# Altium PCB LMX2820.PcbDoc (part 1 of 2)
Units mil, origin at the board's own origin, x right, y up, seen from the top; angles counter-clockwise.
Board outline 4000 x 4000 mil, 4 copper layers (Top Layer, RF GND, Signal GND, Bottom Layer), stack 61.2 mil thick; 127 components, 75 nets, 393 pads, 472 vias.
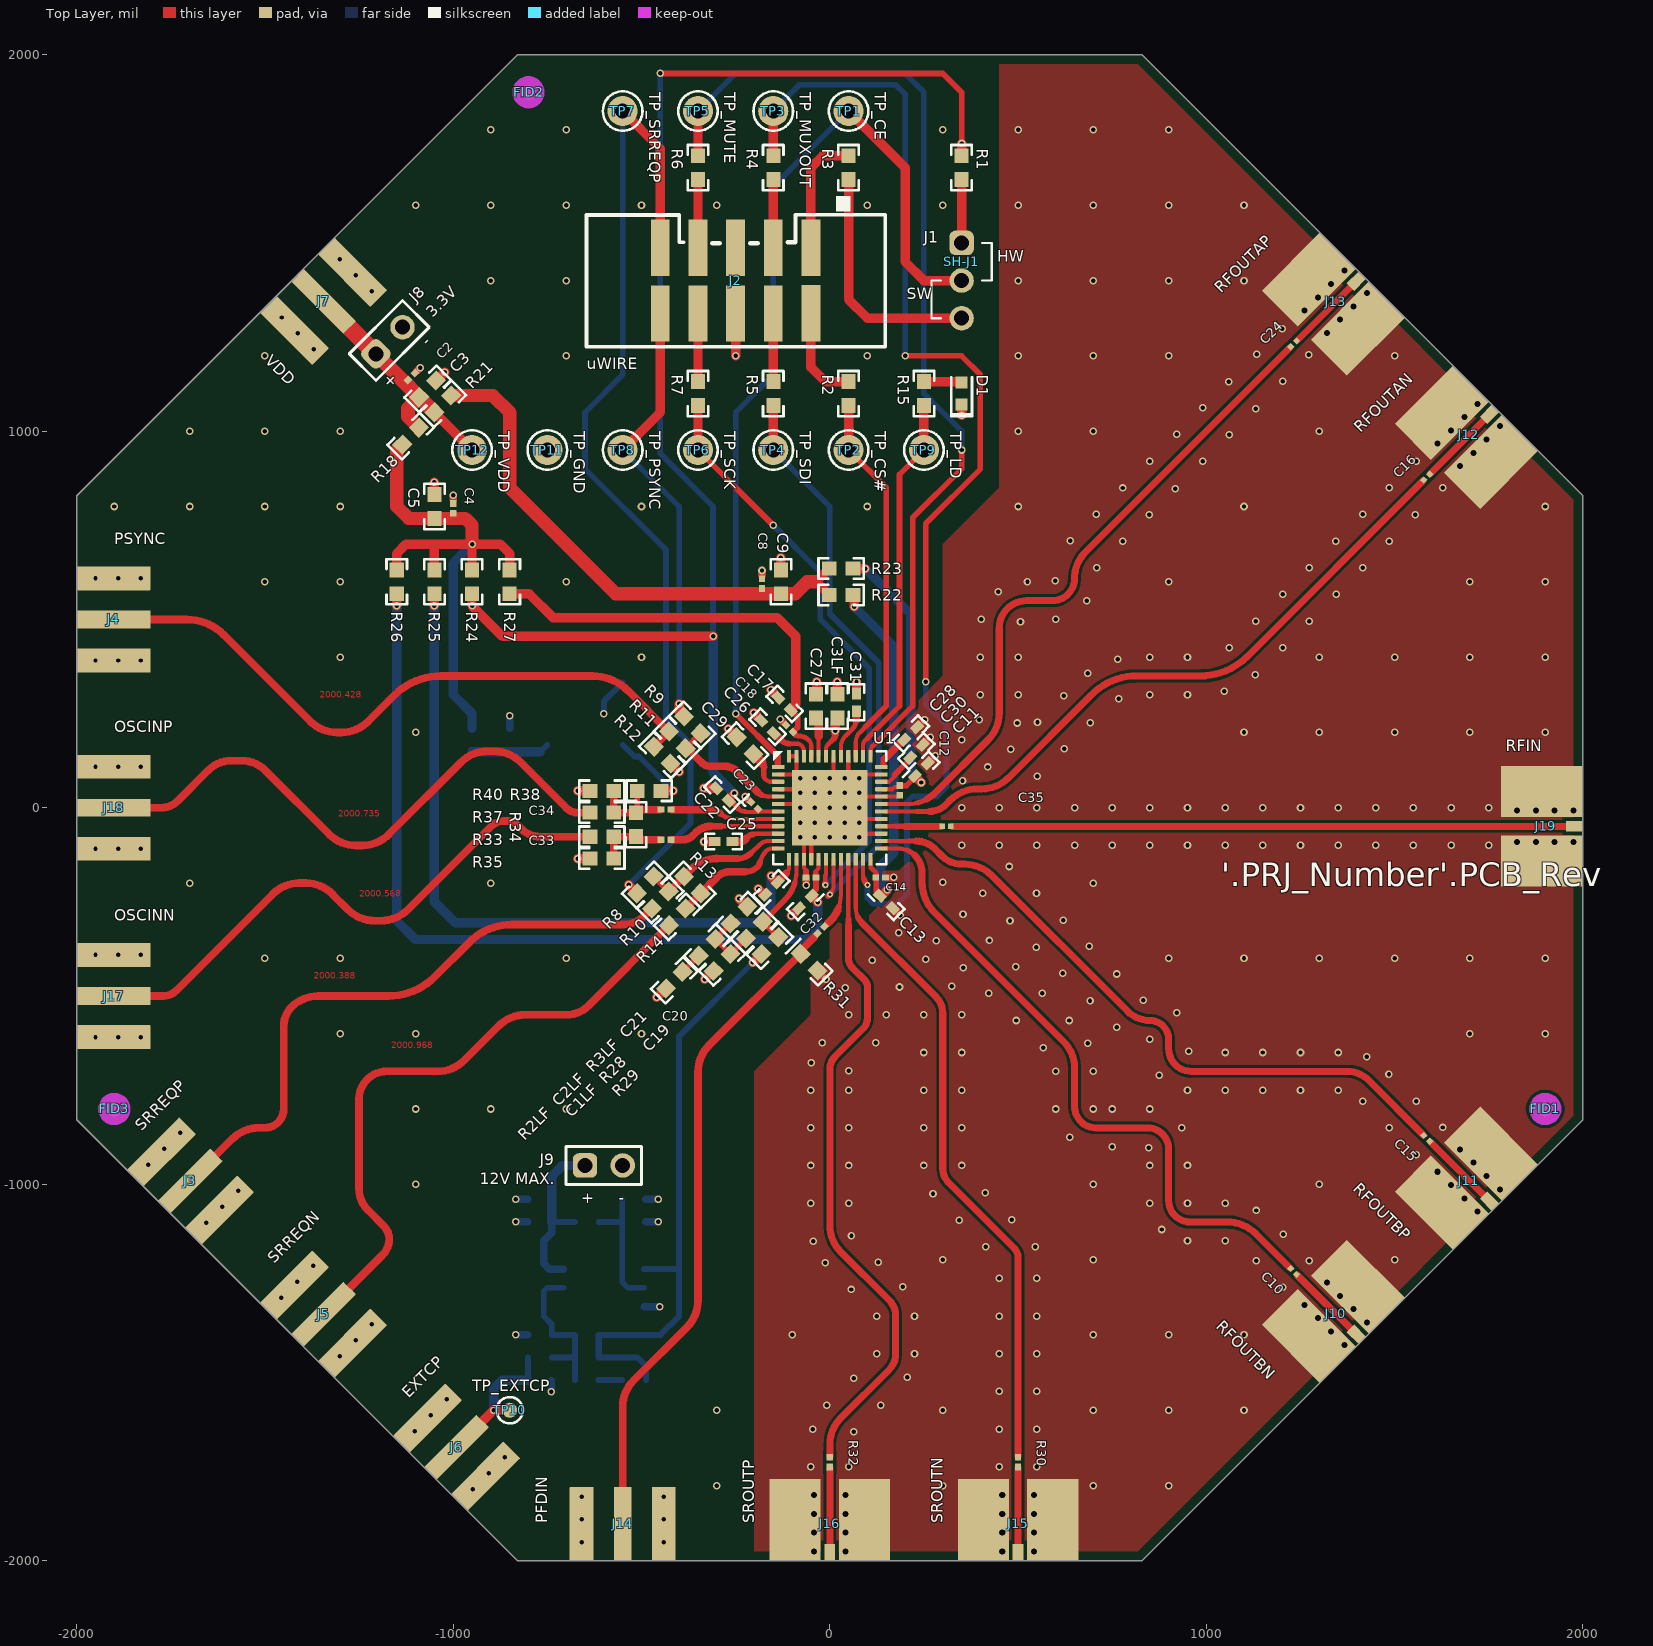
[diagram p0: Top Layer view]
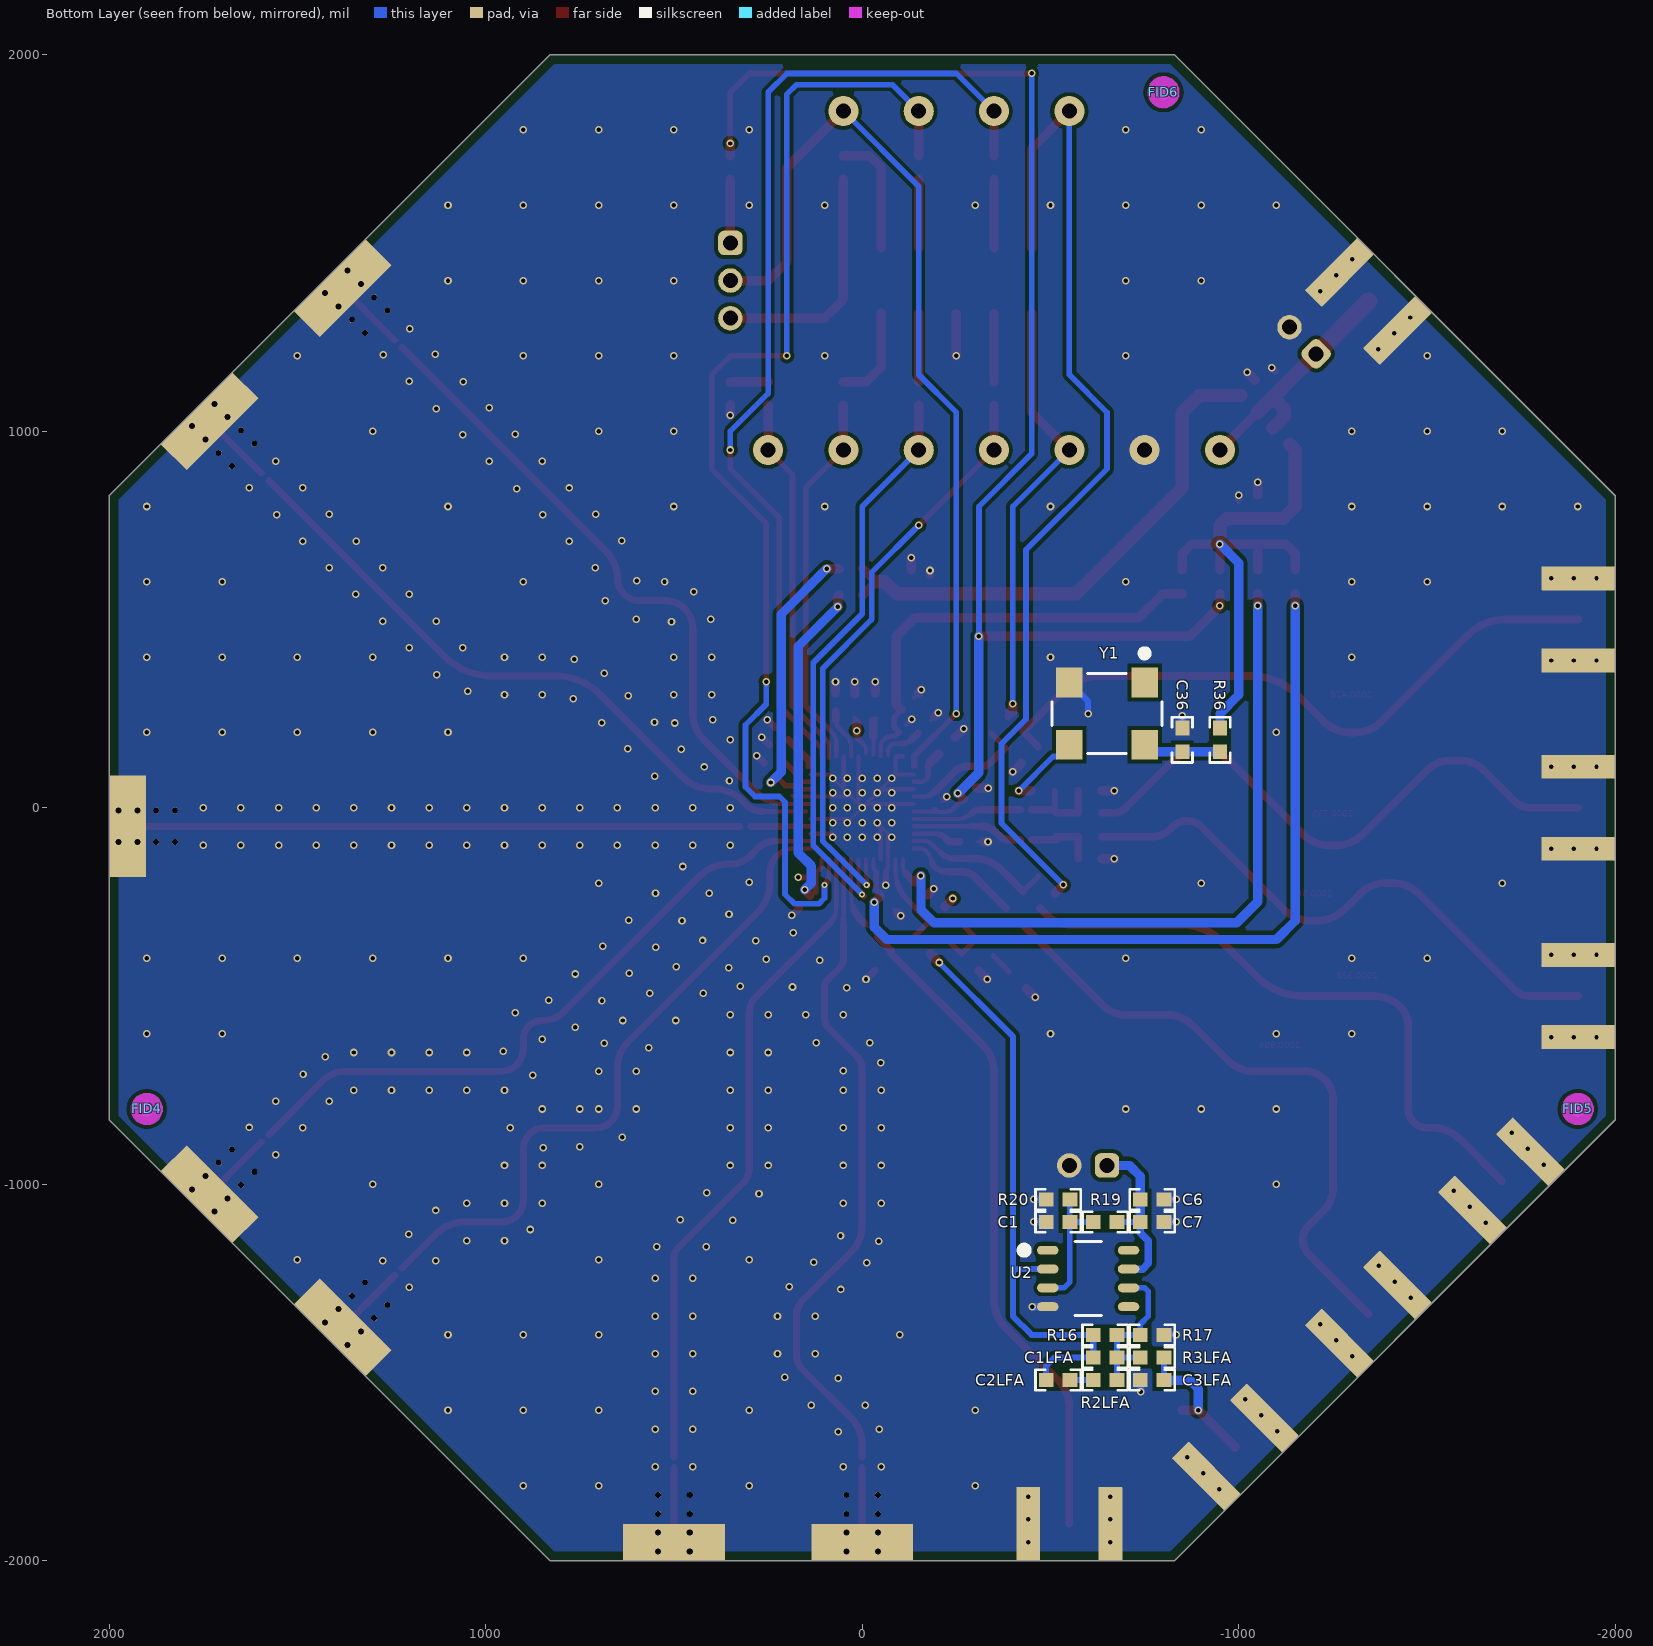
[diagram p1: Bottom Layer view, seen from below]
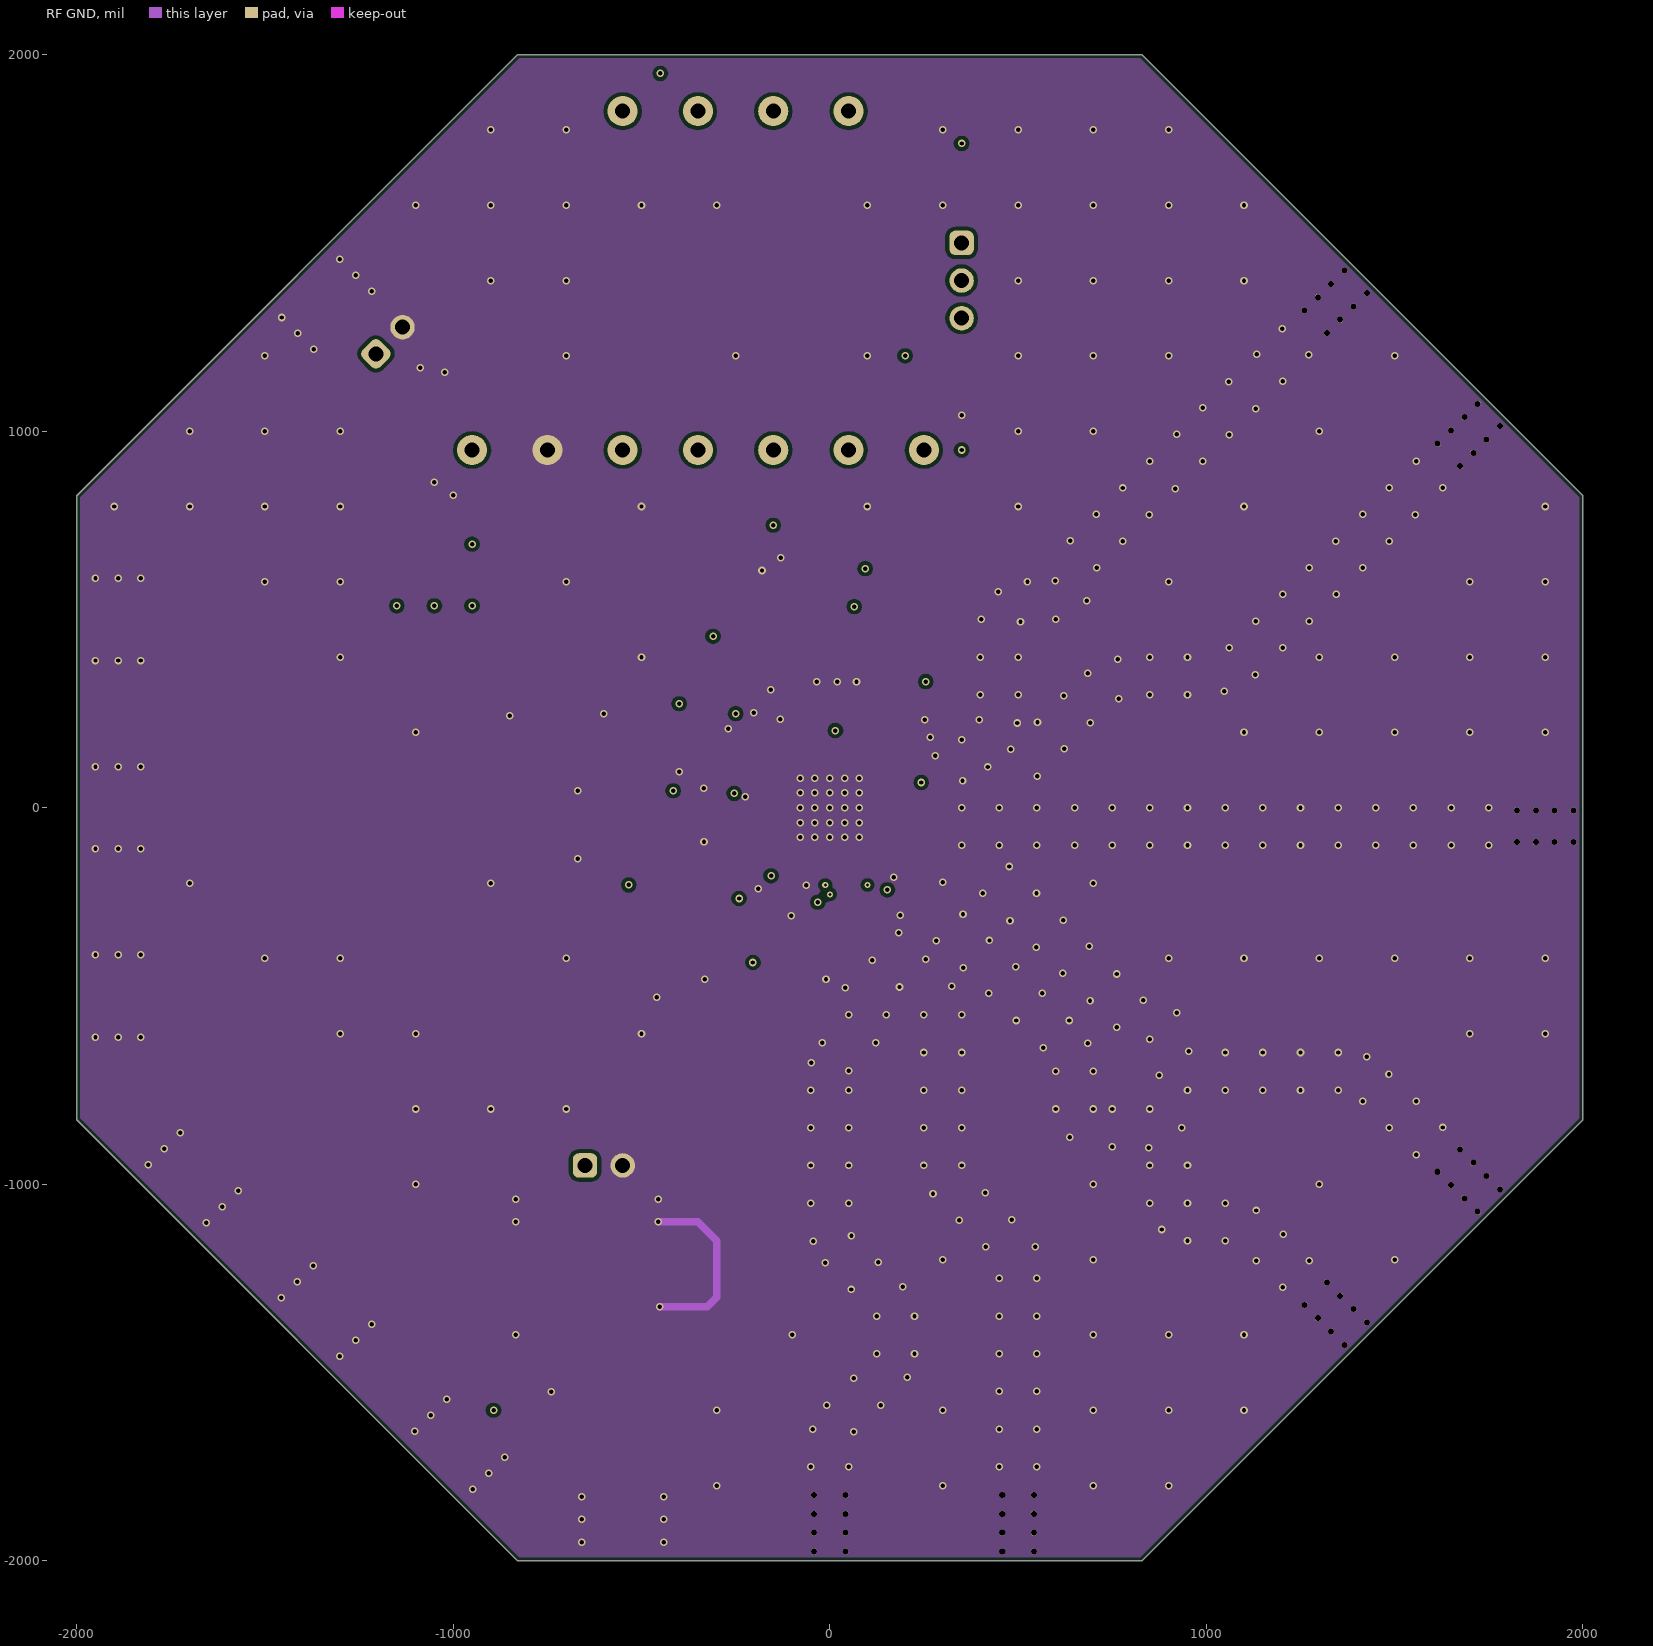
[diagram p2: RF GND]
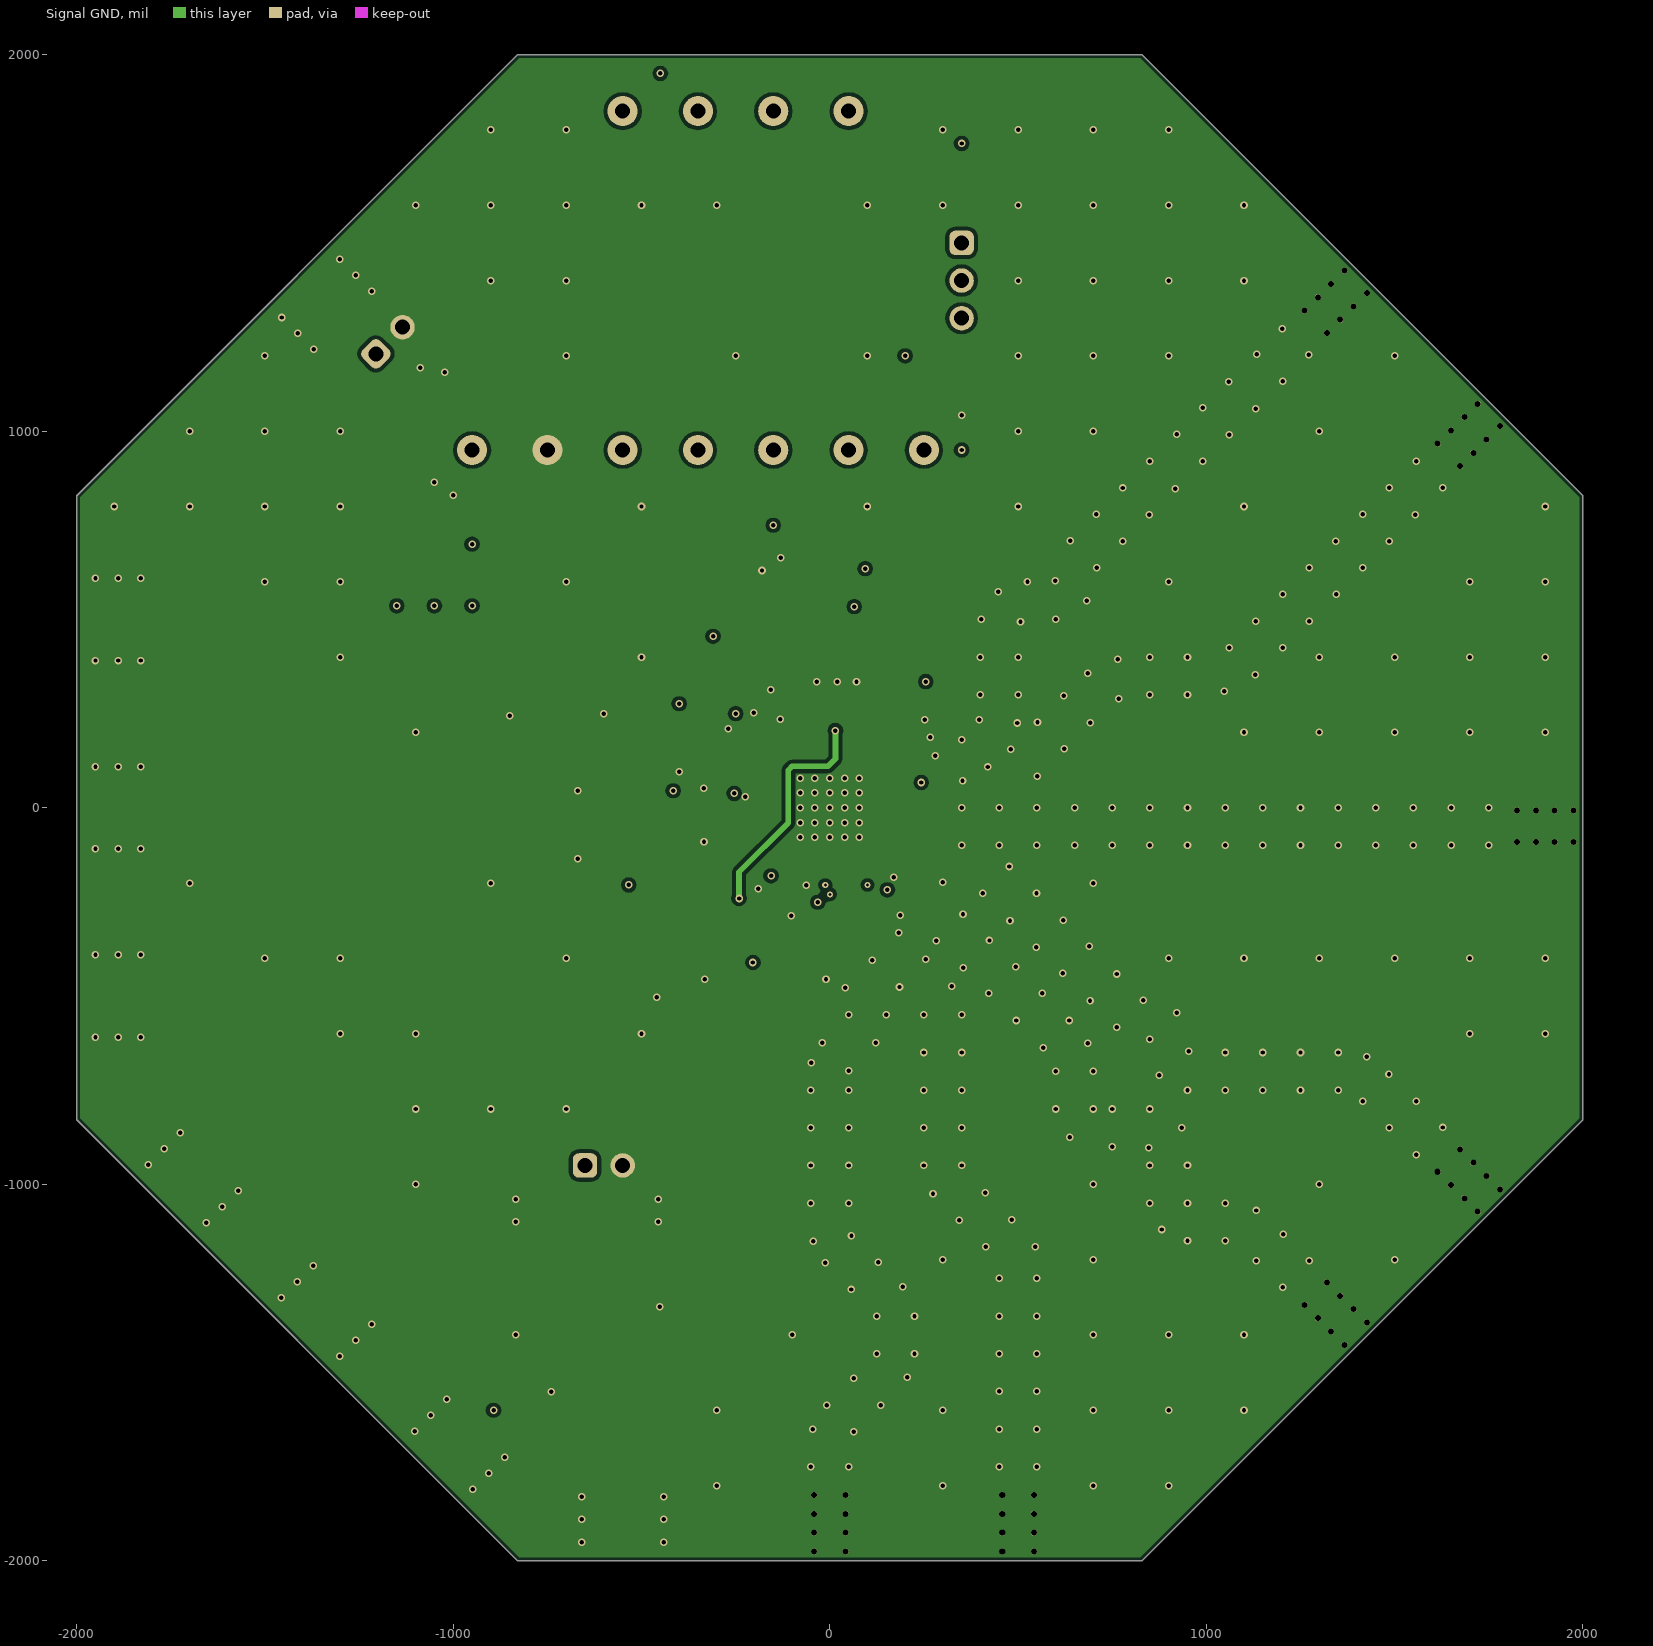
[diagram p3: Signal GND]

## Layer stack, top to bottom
Top Solder: solder mask 0.4, Solder Resist, Dk 3.5
Top Layer: signal copper 1.4
Dielectric 1: prepreg 10, Rogers R04350B, Dk 3.66
RF GND: signal copper 1.4
Dielectric 2: core 22.8, FR-4, Dk 4.2
Signal GND: signal copper 1.4
Dielectric 3: prepreg 22.8, FR-4, Dk 4.2
Bottom Layer: signal copper 1.4
Bottom Solder: solder mask 0.4, Solder Resist, Dk 3.5

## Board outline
-2000,-828.5 -2000,828.5 -828.5,2000 828.5,2000 2000,828.5 2000,-828.5 828.5,-2000 -828.5,-2000

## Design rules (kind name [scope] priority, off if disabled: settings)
AcuteAngle [All] p1: minimum=4.50000000000000E+0001 checktracksonly=FALSE
AssemblyTestPointUsage [All] p1: valid=2
BoardOutlineClearance BoardOutlineClearance_MountingHoles [OnCopper and InComponentClass('Mounting Holes')] p1: gap=39.37 ignorepadtopadclearanceinfootprint=FALSE
BoardOutlineClearance BoardOutlineClearance_Poly [OnCopper and IsPoly and not OnBottomLayer and not OnTopLayer] p2: gap=25 ignorepadtopadclearanceinfootprint=FALSE except(10: Poly-OutlineEdge)
BoardOutlineClearance [OnCopper and Not InComponentClass('Logo') and not InComponentClass('FiducialMark') and not InRegion(1000,500,4000,800) and not InPoly and not InComponent('RFOUTAP')and not InComponent('RFOUTAN')and not InComponent('RFOUTBP')and not InComponent('RFOUTBN')and not InComponent('OSCINP')and not InComponent('OSCINN')and not InComponent('SRREQP')and not InComponent ('SRREQN')and not InComponent ('SROUTP') and not InComponent ('SROUTN') and not InComponent ('PSYNC')and not InComponent('VDD')and not InComponent ('RFIN') and not InComponent ('PFDIN') and not InComponent ('EXTCP')and not IsPad and not InNet('NetJ16_1')and not InNet('NetJ15_1')and not InNet('NetC10_1')and not InNet('NetC15_1')and not InNet('NetJ19_1')and not InNet('NetC16_1')and not InNet('NetC24_1')and not InNet('NetC35_2')] p3: gap=75 ignorepadtopadclearanceinfootprint=FALSE except(25: Track-OutlineEdge Via-OutlineEdge Poly-OutlineEdge)
Clearance Clearance_Keepouts [((IsTrack Or IsArc) And Not InPoly) And IsFree and IsKeepOut vs ((IsTrack Or IsArc) And Not InPoly) And IsFree and IsKeepOut] p1: gap=0 ignorepadtopadclearanceinfootprint=FALSE
Clearance Clearance_Poly [InPolygon and not OnTopLayer] p2: gap=10 ignorepadtopadclearanceinfootprint=TRUE
Clearance Clearance_Poly_Top [InPolygon and OnTopLayer] p3: gap=10 ignorepadtopadclearanceinfootprint=TRUE except(8: Arc-Fill Arc-Poly Arc-Region Track-Fill Track-Poly Track-Region)
Clearance Clearance_FiducialMark [IsKeepOut and InComponentClass('FiducialMark') vs IsPad and InComponentClass('FiducialMark')] p4: gap=0 ignorepadtopadclearanceinfootprint=FALSE
Clearance [All] p5: gap=7.87 ignorepadtopadclearanceinfootprint=TRUE
ComponentClearance ComponentClearance_MountingHoles_FiducialMarks [InComponentClass('Mounting Holes') vs InComponentClass('FiducialMark')] p1: gap=50 collisioncheckmode=3 verticalgap=10 showdistances=FALSE
ComponentClearance ComponentClearance_Shunt [InComponentClass('Header') vs InComponentClass('Shunt')] p2: gap=0 collisioncheckmode=3 verticalgap=0 showdistances=FALSE
ComponentClearance ComponentClearance_Logo [InComponentClass('Logo')] p3: gap=50 collisioncheckmode=3 verticalgap=10 showdistances=FALSE
ComponentClearance ComponentClearance_ScrewToNut [(HasFootprint('NY PMS 440 0025 PH')) vs (HasFootprint('Keystone_1902C'))] p4: gap=5 collisioncheckmode=3 verticalgap=10 showdistances=FALSE
ComponentClearance ComponentClearance_MountingHoles [InComponentClass('Mounting Holes')] p5: gap=250 collisioncheckmode=3 verticalgap=100000 showdistances=FALSE
ComponentClearance ComponentClearance_SmallPassives [HasFootprint('0201*') or HasFootprint('0402*') or HasFootprint('0508') or HasFootprint('0603*') or HasFootprint('0612') or HasFootprint('0805*') or HasFootprint('0815*') or HasFootprint('0830*') or HasFootprint('1206*') or HasFootprint('1210*') or HasFootprint('1808*') or HasFootprint('1812*') or HasFootprint('1825*') or HasFootprint('2010*') or HasFootprint('2220*') or HasFootprint('2225*') or HasFootprint('2512*') or HasFootprint('2728*') or HasFootprint('3518*') vs HasFootprint('0201*') or HasFootprint('0402*') or HasFootprint('0508') or HasFootprint('0603*') or HasFootprint('0612') or HasFootprint('0805*') or HasFootprint('0815*') or HasFootprint('0830*') or HasFootprint('1206*') or HasFootprint('1210*') or HasFootprint('1808*') or HasFootprint('1812*') or HasFootprint('1825*') or HasFootprint('2010*') or HasFootprint('2220*') or HasFootprint('2225*') or HasFootprint('2512*') or HasFootprint('2728*') or HasFootprint('3518*')] p6: gap=14.96 collisioncheckmode=3 verticalgap=10 showdistances=FALSE
ComponentClearance ComponentClearance_THtoSMT [IsThruComponent vs IsSMTComponent] p7: gap=40 collisioncheckmode=3 verticalgap=30 showdistances=FALSE
ComponentClearance ComponentClearance_THtoTH [IsThruComponent vs IsThruComponent] p8: gap=30 collisioncheckmode=3 verticalgap=30 showdistances=FALSE
ComponentClearance [All] p9: gap=30 collisioncheckmode=3 verticalgap=10 showdistances=FALSE
DiffPairsRouting [All] p1: maxlimit=100 minlimit=10 mostfreqgap=10 toplayer_minwidth=15 toplayer_maxwidth=15 toplayer_prefwidth=15 midlayer1_minwidth=15 midlayer1_maxwidth=15 midlayer1_prefwidth=15 midlayer2_minwidth=15 midlayer2_maxwidth=15 midlayer2_prefwidth=15 bottomlayer_minwidth=15 bottomlayer_maxwidth=15 bottomlayer_prefwidth=15 maxuncoupledlength=1000
FabricationTestPointUsage TestPointUsage [All] p1: valid=2 allowmultiple=FALSE
FabricationTestpoint Testpoint [All] p1: side=3 testpointundercomponent=TRUE minsize=40 maxsize=100 preferedsize=60 minholesize=0 maxholesize=40 preferedholesize=32 testpointgrid=1 allowsidetop=TRUE allowsidebottom=TRUE usegrid=TRUE gridtolerance=0.01
FanoutControl Fanout_LCC [IsLCC] p1: bgadir=Out bgaviamode=Centered fanoutstyle=Auto fanoutdirection=Alternating viagrid=1 // Fanout_LCC (Default Rule)
FanoutControl Fanout_BGA [IsBGA] p2: bgadir=Out bgaviamode=Centered fanoutstyle=Auto fanoutdirection=Alternating viagrid=1 // Fanout_BGA (Default Rule)
FanoutControl Fanout_Default [All] p4: bgadir=Out bgaviamode=Centered fanoutstyle=Auto fanoutdirection=Alternating viagrid=1 // Fanout_Default (Default Rule)
FanoutControl Fanout_Small [(CompPinCount < 5)] p5: bgadir=Out bgaviamode=Centered fanoutstyle=Auto fanoutdirection=OutThenIn viagrid=1 // Fanout_Small (Default Rule)
HoleSize [All] p1: absolutevalues=TRUE maxlimit=251 minlimit=7.87 maxpercent=80.000 minpercent=20.000
MinimumAnnularRing MinimumAnnularRing_ThermalPadVias [IsVia and InAnyComponent] p1: minimumring=3.94
MinimumAnnularRing [All] p2: minimumring=4
MinimumSolderMaskSliver MinimumSolderMaskSliver_Logo [InComponentClass('Logo') vs InComponentClass('Logo')] p1: minsoldermaskwidth=0.7
MinimumSolderMaskSliver [All] p2: minsoldermaskwidth=3.94
PlaneConnect [All] p1: planeconnectstyle=Relief reliefexpansion=10 reliefentries=4 reliefconductorwidth=10 reliefairgap=10
PolygonConnect [All] p1: connectstyle=Direct reliefconductorwidth=10 reliefentries=4 polygonreliefangle="90 Angle" airgapwidth=10
RoutingVias ThermalPadVias [IsVia and InAnyComponent] p1: holewidth=7.87 width=19.68 viastyle="Through Hole" minholewidth=7.87 minwidth=19.68 maxholewidth=12.99 maxwidth=23.62
RoutingVias [All] p2: holewidth=13 width=25 viastyle="Through Hole" minholewidth=8 minwidth=15 maxholewidth=18 maxwidth=25
SilkToBoardRegionClearance [Not ((IsComment or IsDesignator) And (Hide <> 'False')) and not InRegion(1000,500,4000,800)] p1:
SilkToSilkClearance SilkToSilkClearance_Pb-FreeLogo [(HasFootprint('Pb-Free_Overlay_Medium') OR HasFootprint('Pb-Free_Overlay_Small')) vs (HasFootprint('Pb-Free_Overlay_Medium') OR HasFootprint('Pb-Free_Overlay_Small'))] p1: silktosilkclearance=0
SilkToSilkClearance [All] p2: silktosilkclearance=3.94
SilkToSolderMaskClearance SilkToComponentPadClearance [(IsPad or IsFill or IsRegion) and InAnycomponent] p1: minsilkscreentomaskgap=5 clearancetoexposedcopper=TRUE
SilkToSolderMaskClearance "Silk to Solder Mask Opening" [All] p2: minsilkscreentomaskgap=3.94 clearancetoexposedcopper=FALSE
SolderMaskExpansion [All] p1: expansion=1.97
UnRoutedNet [All] p1: checkbadconnections=TRUE
Width [All] p1: maxlimit=100 minlimit=6 preferedwidth=10 checkconnectedcopper=TRUE
14 further rules are at their usual default settings.

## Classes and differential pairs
component class Shunt: SH-J1
component class Header: J1 J8 J9
component class LMX2820_SYNTH: C1LF C2LF C3LF C10 C11 C12 C13 C14 C15 C16 C17 C18 C19 C20 C21 C22 C23 C24 C25 C26 C27 C28 C29 C30 C31 C32 C33 C34 C35 C36 J10 J11 J12 J13 J14 J15 J16 J17 J18 J19 R2LF R3LF R22 R23 R24 R25 R26 R27 R28 R29 R30 R31 R32 R33 R34 R35 R36 R37 R38 R40 R300 U1 Y1
component class LMX2820_HW: FID1 FID2 FID3 FID4 FID5 FID6 SH-J1
component class FiducialMark: FID1 FID2 FID3 FID4 FID5 FID6

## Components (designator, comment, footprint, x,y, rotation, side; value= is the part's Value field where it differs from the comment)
C1 "885012206046" 0603 -520,-1100 r180 bottom value=0.1uF
C1LF "885012006012" 0603 -286,-411 r225 top value=470pF
C1LFA "885012206046" 0603 -645,-1460 r180 bottom value=0.1uF
C2 "GRM033R61C104KE84D" 0201_033 -1111,1145 r45 top value=0.1uF
C2LF "885012206070" 0603 -326,-371 r225 top value=0.068uF
C2LFA "885012206046" 0603 -520,-1520 r180 bottom value=0.1uF
C3 "GRM188R61A106KAALD" 0603 -1068,1112.5 r45 top value=10uF
C3LF "885012206036" 0603 20.5,270 r90 top value=2200pF
C3LFA "885012206046" 0603 -770,-1520 r180 bottom value=0.1uF
C4 "GRM033R61C104KE84D" 0201_033 -1000,795 r90 top value=0.1uF
C5 "GRM188R61A106KAALD" 0603 -1050,800 r270 top value=10uF
C6 "885012206046" 0603 -770,-1040 r180 bottom value=0.1uF
C7 "GRM188R61A106KAALD" 0603 -770,-1100 r180 bottom value=10uF
C8 "GRM033R61C104KE84D" 0201_033 -180,595 r90 top value=0.1uF
C9 "GRM188R61A106KAALD" 0603 -130,600 r270 top value=10uF
C10 "ATC530Z104KT10T" 0201_033L 1231.65,-1231.65 r135 top locked value=0.1uF
C11 "GRM155R61E105KA12D" 0402 243,101 r45 top value=1uF
C12 "GRM033R61C104KE84D" 0201_033 186,46 r270 top value=0.1uF
C13 "GRM155R61E105KA12D" 0402 150,-250 r135 top value=1uF
C14 "GRM033R61C104KE84D" 0201_033 135,-185 r180 top value=0.1uF
C15 "ATC530Z104KT10T" 0201_033L 1585.15,-878.15 r135 top locked value=0.1uF
C16 "ATC530Z104KT10T" 0201_033L 1585.3,878.2 r225 top locked value=0.1uF
C17 "GRM155R61E105KA12D" 0402 -120,276 r135 top value=1uF
C18 "GRM033R61C104KE84D" 0201_033 -107,210 r135 top value=0.1uF
C19 "GRM155R61E105KA12D" 0402 -65,-250 r225 top value=1uF
C20 "GRM033R61C104KE84D" 0201_033 -50,-185 r0 top value=0.1uF
C21 "GRM155R61E105KA12D" 0402 -155,-214 r225 top value=1uF
C22 "GRM155R61E105KA12D" 0402 -285,35 r135 top value=1uF
C23 "GRM033R61C104KE84D" 0201_033 -200,5.5 r315 top value=0.1uF
C24 "ATC530Z104KT10T" 0201_033L 1231.75,1231.75 r225 top locked value=0.1uF
C25 "GRM155R61E105KA12D" 0402 -282,-90 r180 top value=1uF
C26 "GRM155R61E105KA12D" 0402 -165,215 r135 top value=1uF
C27 "GRM188R61A106KAALD" 0603 -37,270 r270 top value=10uF
C28 "GRM155R61E105KA12D" 0402 215,197 r225 top value=1uF
C29 "CGA3E3X7R1E474K080AB" 0603 -225,165 r135 top value=0.47uF
C30 "GRM155R61E105KA12D" 0402 230,150 r225 top value=1uF
C31 "GRM155R61E105KA12D" 0402 71,280 r90 top value=1uF
C32 "GRM033R61C104KE84D" 0201_033 -23,-325 r225 top value=0.1uF
C33 "GRM033R61C104KE84D" 0201_033 -435,-85 r180 top value=0.1uF
C34 "GRM033R61C104KE84D" 0201_033 -435,-5 r180 top value=0.1uF
C35 "ATC530Z104KT10T" 0201_033L 310,-49.21 r0 top value=0.1uF
C36 "885012206052" 0603 -850,180 r90 bottom value=1uF
D1 "LTST-C190GKT" LED_LTST-C190 350,1100 r270 top value=Green
FID1 "Fiducial" Fiducial10-20 1900,-800 r0 top
FID2 "Fiducial" Fiducial10-20 -800,1900 r0 top
FID3 "Fiducial" Fiducial10-20 -1900,-800 r0 top
FID4 "Fiducial" Fiducial10-20 1900,-800 r180 bottom
FID5 "Fiducial" Fiducial10-20 -1900,-800 r180 bottom
FID6 "Fiducial" Fiducial10-20 -800,1900 r180 bottom
J1 "TSW-103-07-G-S" TSW-103-07-G-S 350,1400 r270 top
J2 "uWIRE" FCI_52601-S10-8LF -250,1400 r270 top
J3 "SRREQP" FP-CON-SMA-EDGE-S_CONN_JACK-MFG -1900.3,-1193.2 r135 top locked
J4 "PSYNC" FP-CON-SMA-EDGE-S_CONN_JACK-MFG -2187.5,500 r90 top locked
J5 "SRREQN" FP-CON-SMA-EDGE-S_CONN_JACK-MFG -1546.5,-1547 r135 top locked
J6 "EXTCP" FP-CON-SMA-EDGE-S_CONN_JACK-MFG -1193.25,-1900.25 r135 top locked
J7 "VDD" FP-CON-SMA-EDGE-S_CONN_JACK-MFG -1546.5,1547 r45 top locked
J8 "3.3V" TSW-102-07-G-S -1170,1240.75 r45 top
J9 "12V MAX." TSW-102-07-G-S -600,-950 r0 top
J10 "RFOUTBN" Johnson_142-0771-831 1414.25,-1414.25 r225 top locked
J11 "RFOUTBP" Johnson_142-0771-831 1767.8,-1060.7 r225 top locked
J12 "RFOUTAN" Johnson_142-0771-831 1767.8,1060.7 r315 top locked
J13 "RFOUTAP" Johnson_142-0771-831 1414.25,1414.25 r315 top locked
J14 "PFDIN" FP-CON-SMA-EDGE-S_CONN_JACK-MFG -550,-2187.5 r180 top locked
J15 "SROUTN" Johnson_142-0771-831 500,-2000 r180 top locked
J16 "SROUTP" Johnson_142-0771-831 0,-2000 r180 top locked
J17 "OSCINN" FP-CON-SMA-EDGE-S_CONN_JACK-MFG -2187.5,-500 r90 top locked
J18 "OSCINP" FP-CON-SMA-EDGE-S_CONN_JACK-MFG -2187.5,0 r90 top locked
J19 "RFIN" Johnson_142-0771-831 2000,-49.21 r270 top locked
R1 "CRCW06031K00JNEA" 0603 350,1700 r90 top value=1.0k
R2 "CRCW060333R0JNEA" 0603 50,1100 r270 top value=33
R2LF "CRCW060368R1FKEA" 0603 -413,-458 r45 top value=68.1
R2LFA "CRCW060333R0JNEA" 0603 -645,-1520 r180 bottom value=33
R3 "CRCW060333R0JNEA" 0603 50,1700 r90 top value=33
R3LF "CRCW060318R2FKEA" 0603 -241,-285 r225 top value=18.2
R3LFA "CRCW06030000Z0EA" 0603 -770,-1460 r180 bottom value=0
R4 "CRCW060333R0JNEA" 0603 -150,1700 r90 top value=33
R5 "CRCW060333R0JNEA" 0603 -150,1100 r270 top value=33
R6 "CRCW060333R0JNEA" 0603 -350,1700 r90 top value=33
R7 "CRCW060333R0JNEA" 0603 -350,1100 r270 top value=33
R8 "CRCW060333R0JNEA" 0603 -490,-205 r45 top value=33
R9 "CRCW060333R0JNEA" 0603 -365,220 r315 top value=33
R10 "CRCW06030000Z0EA" 0603 -450,-245 r225 top value=0
R11 "CRCW060318R0JNEA" 0603 -405,180 r315 top value=18
R12 "CRCW060349R9FKEA" 0603 -445,140 r135 top value=49.9
R13 "CRCW0603102RFKEA" 0603 -365,-205 r315 top value=102
R14 "CRCW06030000Z0EA" 0603 -405,-290 r225 top value=0
R15 "CRCW0603330RJNEA" 0603 250,1100 r270 top value=330
R16 "CRCW06030000Z0EA" 0603 -645,-1400 r180 bottom value=0
R17 "CRCW06030000Z0EA" 0603 -770,-1400 r180 bottom value=0
R18 "CRCW06030000Z0EA" 0603 -1113,987 r45 top value=0
R19 "CRCW06030000Z0EA" 0603 -645,-1100 r0 bottom value=0
R20 "CRCW06030000Z0EA" 0603 -520,-1040 r180 bottom value=0
R21 "CRCW06030000Z0EA" 0603 -1027.75,1072.25 r45 top value=0
R22 "CRCW06030000Z0EA" 0603 30.02,565.03 r180 top value=0
R23 "CRCW06030000Z0EA" 0603 30.02,635.03 r180 top value=0
R24 "CRCW06030000Z0EA" 0603 -950,600 r90 top value=0
R25 "CRCW06030000Z0EA" 0603 -1050,600 r90 top value=0
R26 "CRCW06030000Z0EA" 0603 -1150,600 r90 top value=0
R27 "CRCW06030000Z0EA" 0603 -850,600 r90 top value=0
R28 "CRCW06030000Z0EA" 0603 -200,-325 r45 top value=0
R29 "CRCW06030000Z0EA" 0603 -159,-366 r45 top value=0
R30 "CRCW02010000Z0ED" 0201 500,-1738 r270 top locked value=0
R31 "CRCW060349R9FKEA" 0603 -55,-410 r135 top value=49.9
R32 "CRCW02010000Z0ED" 0201 0,-1738 r270 top locked value=0
R33 "CRCW06030000Z0EA" 0603 -605,-77 r0 top value=0
R34 "CRCW0603102RFKEA" 0603 -515,-45 r90 top value=102
R35 "CRCW060349R9FKEA" 0603 -605,-135 r0 top value=49.9
R36 "CRCW06033R30JNEA" 0603 -950,180 r90 bottom value=3.3
R37 "CRCW06030000Z0EA" 0603 -605,-13 r0 top value=0
R38 "CRCW06030000Z0EA" 0603 -480,45 r180 top value=0
R40 "CRCW060349R9FKEA" 0603 -605,45 r180 top value=49.9
SH-J1 "SNT-100-BK-G" SNT-100-BK-G 350,1450 r90 top value=1x2
TP1 "TP_CE" Keystone5002 50,1850 r180 top
TP2 "TP_CS#" Keystone5002 50,950 r180 top
TP3 "TP_MUXOUT" Keystone5002 -150,1850 r180 top
TP4 "TP_SDI" Keystone5002 -150,950 r180 top
TP5 "TP_MUTE" Keystone5002 -350,1850 r180 top
TP6 "TP_SCK" Keystone5002 -350,950 r180 top
TP7 "TP_SRREQP" Keystone5002 -550,1850 r90 top
TP8 "TP_PSYNC" Keystone5002 -550,950 r180 top
TP9 "TP_LD" Keystone5002 250,950 r90 top
TP10 "TP_EXTCP" TESTPOINT -850,-1600 r0 top
TP11 "TP_GND" Keystone5001 -750,950 r90 top
TP12 "TP_VDD" Keystone5000 -950,950 r90 top
U1 "LMX2820" RTC0048A 0,0 r0 top locked
U2 "LME49710MA" D0008A_N -600,-1250 r180 bottom
Y1 "CWX813-100.0M" OSC_CWX -650,250 r270 bottom

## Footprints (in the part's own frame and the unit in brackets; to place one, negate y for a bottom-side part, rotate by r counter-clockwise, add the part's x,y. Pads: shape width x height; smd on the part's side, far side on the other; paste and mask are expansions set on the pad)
0201 [mm] "Data from Kemet datasheet CC101_COM dated 7/28/11"
  rect 0.46x0.42 smd mask+0.048: 1(-0.33,0) 2(0.33,0)
  body extent -0.31,-0.16 0.31,0.16, height 0.26
0201_033 [mm] "SMD, 2-Leads, Height 0.33mm"
  rect 0.46x0.42 smd mask+0.048: 1(-0.33,0) 2(0.33,0)
  body extent -0.31,-0.16 0.31,0.16, height 0.33
0201_033L [mm] "0201"
  rect 0.36x0.356 smd mask+0.048: 1(-0.28,0) 2(0.28,0)
  body extent -0.31,-0.16 0.31,0.16, height 0.33
0402 [mm] "0402 from SM-752 data"
  rect 0.8x0.6 smd: 1(-0.6,0) 2(0.6,0)
  silkscreen extent -1.22,-0.52 1.22,0.52, body extent -0.55,-0.3 0.55,0.3, height 0.6
0603 [mm] "0603 from SM-752 data"
  rect 1x0.95 smd: 1(-0.8,0) 2(0.8,0)
  silkscreen extent -1.52,-0.69 1.52,0.69, body extent -0.87,-0.47 0.87,0.47, height 1
D0008A_N [mm] "SOIC, 8-Leads, Body 4.9x3.9mm, Pitch 1.27mm, IPC Medium Density"
  oval 1.45x0.6 smd: 1(-2.725,1.905) 2(-2.725,0.635) 3(-2.725,-0.635) 4(-2.725,-1.905) 5(2.725,-1.905) 6(2.725,-0.635) 7(2.725,0.635) 8(2.725,1.905)
  silkscreen extent -0.9,-2.5 0.9,2.5, body extent -3,-2.45 3,2.45, height 1.63
FCI_52601-S10-8LF [mil] "FCI Electronics"
  rect 150x50 smd: 1(-87.5,200) 2(86.5,200) 3(-87.5,100) 4(87.5,100) 5(-87.5,0) 6(87.5,0) 7(-87.5,-100) 8(87.5,-100) 9(-87.5,-200) 10(87.5,-200)
  silkscreen extent -224,-396 176,397, body extent -172,-395 173,395, height 496
Fiducial10-20 [mm]
  round 1 smd mask+0.5: 1(0,0)
  Top Layer keep-out circle w1.178: c0,0 r0.5
FP-CON-SMA-EDGE-S_CONN_JACK-MFG [mm]
  rrect8% 1.2x5 smd paste+0 mask+0: 1(0,-7.26)
  rrect6% 1.6x5 smd paste+0 mask+0: 2(-2.77,-7.26) 3(2.77,-7.26)
  rrect6% 1.6x5 smd far side paste+0 mask+0: 4(-2.77,-7.26) 5(2.77,-7.26)
  body extent -3.28,-9.86 3.28,4.86, height 0.25
Johnson_142-0771-831 [mil] "JACK, SMA, 50 Ohm, Gold, Edge Mount"
  rect 28.5x45 smd: 1(0,-22.5)
  rect 135.75x218 smd: 2(-92.13,-109) 3(92.13,-109)
  round 16 hole 16: 2(-42,-25) 2(-42,-175) 2(-42,-75) 2(-42,-125) 3(42,-125) 3(42,-25) 3(42,-75) 3(42,-175)
  rect 270x97.5 smd far side: 4(0,-48.75)
  body extent -124,-179 123,375, height 131
Keystone5000 [mil] "For Keystone 500x miniature loop terminals"
  round 80 hole 40: 1(0,0)
  silkscreen extent -52,-52 52,52, body extent -49,-49 49,49, height 182
Keystone5001 [mil] "For Keystone 500x miniature loop terminals"
  round 80 hole 40: 1(0,0)
  silkscreen extent -52,-52 52,52, body extent -49,-49 49,49, height 182
Keystone5002 [mil] "For Keystone 500x miniature loop terminals"
  round 80 hole 40: 1(0,0)
  silkscreen extent -52,-52 52,52, body extent -49,-49 49,49, height 182
LED_LTST-C190 [mm] "Lite-On"
  rect 0.8x0.8 smd: 1(-0.75,0) 2(0.75,0)
  silkscreen extent -1.1,-0.7 1.52,0.7, body extent -0.85,-0.45 0.85,0.45, height 0.9
OSC_CWX [mm] "CONNOR WINFIELD"
  rect 2x1.8 smd: 1(-2.1,2.54) 2(-2.1,-2.54) 3(2.1,-2.54) 4(2.1,2.54)
  silkscreen extent -4.29,-3.7 2.7,3.7, body extent -2.65,-3.65 2.65,3.65, height 1.31
RTC0048A [mm] "PVQFN, 64-Leads, Body 7x7mm, Pitch 0.5mm"
  rrect36% 0.85x0.28 smd paste-0.28: 1(-3.475,2.75) 2(-3.475,2.25) 3(-3.475,1.75) 4(-3.475,1.25) 5(-3.475,0.75) 6(-3.475,0.25) 7(-3.475,-0.25) 8(-3.475,-0.75) 9(-3.475,-1.25) 10(-3.475,-1.75) 11(-3.475,-2.25) 12(-3.475,-2.75) 25(3.475,-2.75) 26(3.475,-2.25) 27(3.475,-1.75) 28(3.475,-1.25) 29(3.475,-0.75) 30(3.475,-0.25) 31(3.475,0.25) 32(3.475,0.75) 33(3.475,1.25) 34(3.475,1.75) 35(3.475,2.25) 36(3.475,2.75)
  rrect36% 0.28x0.85 smd paste-0.28: 13(-2.75,-3.475) 14(-2.25,-3.475) 15(-1.75,-3.475) 16(-1.25,-3.475) 17(-0.75,-3.475) 18(-0.25,-3.475) 19(0.25,-3.475) 20(0.75,-3.475) 21(1.25,-3.475) 22(1.75,-3.475) 23(2.25,-3.475) 24(2.75,-3.475) 37(2.75,3.475) 38(2.25,3.475) 39(1.75,3.475) 40(1.25,3.475) 41(0.75,3.475) 42(0.25,3.475) 43(-0.25,3.475) 44(-0.75,3.475) 45(-1.25,3.475) 46(-1.75,3.475) 47(-2.25,3.475) 48(-2.75,3.475)
  rrect2% 5.1x5.1 smd paste-5.1: 49(0,0)
  body extent -3.55,-3.55 3.55,3.55, height 0.9
SNT-100-BK-G [mil] "Samtec STEP model"
  round 1 on Mech3: 0(0,0)
  body extent -100,-50 100,50, height 344
TESTPOINT [mil]
  round 40 smd: 1(0,0)
  silkscreen extent -35,-35 35,35
TSW-102-07-G-S [mm] "Samtec 100mil, 1x2, 230 mil above insulator"
  rrect50% 1.65x1.65 hole 1.016: 1(-1.27,0)
  round 1.65 hole 1.016: 2(1.27,0)
  silkscreen extent -2.54,-1.27 2.54,1.27, body extent -2.54,-1.27 2.54,1.27, height 8.38
TSW-103-07-G-S [mm] "Samtec 100mil, 1x3, 230 mil above insulator"
  rrect50% 1.65x1.65 hole 1.016: 1(-2.54,0)
  round 1.65 hole 1.016: 2(0,0) 3(2.54,0)
  body extent -3.81,-1.27 3.81,1.27, height 8.38

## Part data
C1 C1LFA C2LFA C3LFA C6: library part CMP-0006829-4, "CAP, CERM, 0.1 uF, 16 V, +/- 10%, X7R, 0603", Cap_Case=0603, Manufacturer="Wurth Elektronik", Supplier Part Number 1=710-885012206046, TempCo=X7R, Tolerance_%=10%, Value1=Unknown, Value2=16V, ValueDisplayed=0.1µF
C1LF: library part CMP-0080734-1, "CAP, CERM, 470 pF, 10 V,+/- 5%, C0G/NP0, 0603", Cap_Case=0603, Manufacturer="Wurth Elektronik", Supplier Part Number 1=732-7756-1-ND, TempCo=C0G/NP0, Tolerance_%=5%, Value2=10V, ValueDisplayed=470pF
C2 C4 C8 C12 C14 C18 C20 C23 C32 C33 C34: library part CMP-0009717-2, "CAP, CERM, 0.1 uF, 16 V, +/- 10%, X5R, 0201", Cap_Case=0201, Manufacturer=MuRata, Supplier Part Number 1=490-9985-1-ND, TempCo=X5R, Tolerance_%=10%, Value1=Unknown, Value2=16V, ValueDisplayed=0.1µF
C2LF: library part CMP-0750069-1, "CAP, CERM, 0.068 µF, 25 V,+/- 10%, X7R, 0603", Cap_Case=0603, Manufacturer="Wurth Elektronik", TempCo=X7R, Tolerance_%=10%, Value2=25V, ValueDisplayed=0.068µF
C3 C5 C7 C9 C27: library part CMP-0086193-1, "CAP, CERM, 10 µF, 10 V,+/- 10%, X5R, 0603", Cap_Case=0603, Manufacturer=MuRata, TempCo=X5R, Tolerance_%=10%, Value2=10V, ValueDisplayed=10µF
C3LF: library part CMP-0006827-4, "CAP, CERM, 2200 pF, 16 V, +/- 10%, X7R, 0603", Cap_Case=0603, Manufacturer="Wurth Elektronik", Supplier Part Number 1=710-885012206036, TempCo=X7R, Tolerance_%=10%, Value1=Unknown, Value2=16V, ValueDisplayed=2200pF
C10 C15 C16 C24 C35: library part CMP-0076713-1, "CAP, CERM, 0.1 µF, 10 V,+/- 10%, X5R, 0201", Cap_Case=0201, Manufacturer="American Technical Ceramics", PartNumber=530Z104KT10T, Supplier Part Number 1=1284-1882-1-ND, TempCo=X5R, Tolerance_%=10%, Value2=10V, ValueDisplayed=0.1µF
C11 C13 C17 C19 C21 C22 C25 C26 C28 C30 C31: library part CMP-0006608-2, "CAP, CERM, 1 uF, 25 V, +/- 10%, X5R, 0402", Cap_Case=0402, Manufacturer=MuRata, Supplier Part Number 1=490-10017-1-ND, TempCo=X5R, Tolerance_%=10%, Value1=Unknown, Value2=25V, ValueDisplayed=1µF
C29: library part CMP-0007092-5, "CAP, CERM, 0.47 uF, 25 V, +/- 10%, X7R, AEC-Q200 Grade 1, 0603", Cap_Case=0603, Manufacturer=TDK, Supplier Part Number 1=445-6929-1-ND, TempCo=X7R, Tolerance_%=10%, Value1=Unknown, Value2=25V, ValueDisplayed=0.47uF
C36: library part CMP-0006831-4, "CAP, CERM, 1 uF, 16 V, +/- 10%, X7R, 0603", Cap_Case=0603, Manufacturer="Wurth Elektronik", Supplier Part Number 1=710-885012206052, TempCo=X7R, Tolerance_%=10%, Value1=Unknown, Value2=16V, ValueDisplayed=1uF
D1: library part CMP-0002827-3, "LED, Green, SMD", Color=green, Manufacturer=Lite-On, Power_TotalModule=100mW, Value1=0.1W, Value2=2.1V
FID1 FID2 FID3 FID4 FID5 FID6: library part CMP-0077181-1, "Fiducial mark.  There is nothing to buy or mount.", Manufacturer=N/A
J1: library part CMP-0075407-2, "Header, 100mil, 3x1, Gold, TH", Color=Black, Current_A=6.3A, Manufacturer=Samtec, Supplier Part Number 1=SAM1029-03-ND, Voltage_V=550V
J2: library part CMP-0055434-2, "Header (shrouded), 100mil, 5x2, Gold, SMT", Manufacturer=FCI, PartNumber=52601-S10-8LF, Supplier Part Number 1=609-3593-ND
J3 J4 J5 J6 J7 J14 J17 J18: library part CMP-0088000-4, "CONN SMA JACK STR EDGE MNT", Manufacturer="RF Solutions Ltd.", PartNumber=CON-SMA-EDGE-S
J8 J9: library part CMP-0075405-3, "Header, 100mil, 2x1, Gold, TH", Color=Black, Current_A=6.3A, Manufacturer=Samtec, PartNumber=TSW-102-07-G-S, Supplier Part Number 1=SAM1029-02-ND, Voltage_V=550V
J10 J11 J12 J13 J15 J16 J19: library part CMP-0055844-3, "JACK, SMA, 50 Ohm, Gold, Edge Mount", Color=Gold, Manufacturer="Cinch Connectivity", PartNumber=142-0771-831, Supplier Part Number 1=J808-ND, Voltage_V=170V
R1: library part CMP-0025729-4, "RES, 1.0 k, 5%, 0.1 W, AEC-Q200 Grade 0, 0603", Manufacturer=Vishay-Dale, Power_W=100mW, Supplier Part Number 1=541-1.0KGCT-ND, TempCo="200 ppm/C", Tolerance_%=5%, Value2=0.1W, Value_Code=1k00, ValueDisplayed=1.0k
R2 R2LFA R3 R4 R5 R6 R7 R8 R9: library part CMP-0025787-4, "RES, 33, 5%, 0.1 W, AEC-Q200 Grade 0, 0603", Manufacturer=Vishay-Dale, Power_W=100mW, Supplier Part Number 1=541-33GCT-ND, TempCo="200 ppm/C", Tolerance_%=5%, Value2=0.1W, Value_Code=33R0, ValueDisplayed=33
R2LF: library part CMP-0022553-4, "RES, 68.1, 1%, 0.1 W, AEC-Q200 Grade 0, 0603", Manufacturer=Vishay-Dale, Power_W=100mW, Supplier Part Number 1=541-68.1HCT-ND, TempCo="100 ppm/C", Tolerance_%=1%, Value2=0.1W, Value_Code=68R1, ValueDisplayed=68.1
R3LF: library part CMP-0022099-4, "RES, 18.2, 1%, 0.1 W, AEC-Q200 Grade 0, 0603", Manufacturer=Vishay-Dale, Power_W=100mW, Supplier Part Number 1=541-18.2HCT-ND, TempCo="100 ppm/C", Tolerance_%=1%, Value2=0.1W, Value_Code=18R2, ValueDisplayed=18.2
R3LFA R10 R14 R16 R17 R18 R19 R20 R21 R22 R23 R24 R25 R26 R27 R28 R29 R33 R37 R38: library part CMP-0025697-4, "RES, 0, 5%, 0.1 W, AEC-Q200 Grade 0, 0603", Manufacturer=Vishay-Dale, Power_W=100mW, Supplier Part Number 1=541-0.0GCT-ND, TempCo="200 ppm/C", Tolerance_%=5%, Value2=0.1W, Value_Code=0000, ValueDisplayed=0
R11: library part CMP-0025728-4, "RES, 18, 5%, 0.1 W, AEC-Q200 Grade 0, 0603", Manufacturer=Vishay-Dale, Power_W=100mW, Supplier Part Number 1=541-18GCT-ND, TempCo="200 ppm/C", Tolerance_%=5%, Value2=0.1W, Value_Code=18R0, ValueDisplayed=18
R12 R31 R35 R40: library part CMP-0022448-4, "RES, 49.9, 1%, 0.1 W, AEC-Q200 Grade 0, 0603", Manufacturer=Vishay-Dale, Power_W=100mW, Supplier Part Number 1=541-49.9HCT-ND, TempCo="100 ppm/C", Tolerance_%=1%, Value2=0.1W, Value_Code=49R9, ValueDisplayed=49.9
R13 R34: library part CMP-0021993-5, "RES, 102, 1%, 0.1 W, AEC-Q200 Grade 0, 0603", Manufacturer=Vishay-Dale, Power_W=100mW, Supplier Part Number 1=541-102HCT-ND, TempCo="100 ppm/C", Tolerance_%=1%, Value2=0.1W, Value_Code=102R, ValueDisplayed=102
R15: library part CMP-0025785-4, "RES, 330, 5%, 0.1 W, AEC-Q200 Grade 0, 0603", Manufacturer=Vishay-Dale, Power_W=100mW, Supplier Part Number 1=541-330GCT-ND, TempCo="200 ppm/C", Tolerance_%=5%, Value2=0.1W, Value_Code=330R, ValueDisplayed=330
R30 R32: library part CMP-0027008-4, "RES, 0, 5%, 0.05 W, 0201", Manufacturer=Vishay-Dale, Power_W=50mW, Supplier Part Number 1=72M6743, TempCo=ppm/C, Tolerance_%=5%, Value2=0.05W, Value_Code=0000, ValueDisplayed=0
R36: library part CMP-0025805-4, "RES, 3.3, 5%, 0.1 W, AEC-Q200 Grade 0, 0603", Manufacturer=Vishay-Dale, Power_W=100mW, Supplier Part Number 1=541-3.3GCT-ND, TempCo="200 ppm/C", Tolerance_%=5%, Value2=0.1W, Value_Code=3R30, ValueDisplayed=3.3
SH-J1: library part CMP-0003623-3, "Shunt, 100mil, Gold plated, Black", Alternate Manufacturer=3M, Alternate PartNumber=969102-0000-DA, Manufacturer=Samtec, Supplier Part Number 1=SAM8858-ND
TP1 TP2 TP3 TP4 TP5 TP6 TP7 TP8 TP9: library part CMP-0055139-1, "Test Point, Miniature, White, TH", Color=White, Manufacturer=Keystone, PartNumber=5002, Supplier Part Number 1=36-5002-ND
TP10: library part CMP-0078143-3, "TEST POINT.  No entry in BOM.", Manufacturer=N/A
TP11: library part CMP-0055138-1, "Test Point, Miniature, Black, TH", Color=Black, Manufacturer=Keystone, PartNumber=5001, Supplier Part Number 1=36-5001-ND
TP12: library part CMP-0055137-1, "Test Point, Miniature, Red, TH", Color=Red, Manufacturer=Keystone, PartNumber=5000, Supplier Part Number 1=36-5000-ND
U1: library part CMP-0750054-4, "22-GHz Wideband PLLatinum™ RF Synthesizer With Phase Synchronization and JESD204B Support, RTC0048A (PVQFN-64)", Alternate Manufacturer="Texas Instruments", PartNumber=LMX2820RTCR
U2: library part CMP-0068996-2, "High Performance, High Fidelity Audio Operational Amplifier, 8-pin Narrow SOIC, Pb-Free", Manufacturer="Texas Instruments", PartNumber=LME49710MA/NOPB
Y1: library part CMP-0004571-3, "OSC 100.0000 MHz 3.3V +-25PPM SMD", Frequency_Fixed=100MHz, Frequency Stability=+/-25ppm, Manufacturer=Connor-Winfield, Supplier Part Number 1=CW547CT-ND

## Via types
v1: diameter 20, hole 11.81, Top Layer to Bottom Layer, tented both sides, 469 vias
v2: diameter 16, hole 8, Top Layer to Bottom Layer, tented both sides, 3 vias

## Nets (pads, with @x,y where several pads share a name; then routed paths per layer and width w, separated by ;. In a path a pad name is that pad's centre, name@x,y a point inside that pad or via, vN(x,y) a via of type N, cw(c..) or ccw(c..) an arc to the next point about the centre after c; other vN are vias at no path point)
CE: J1.2 TP1.1 U1.1 | length 2574.3
  Top Layer w10: U1.1@-142,108.46 -142,137 ; U1.1@-134.35,107.93 -134.35,136.47
  Top Layer w15: v1(-250,250) -136.81,136.81
  Top Layer w25: TP1.1@50,1850 200,1700 200,1450 250,1400 J1.2@350,1400
  Bottom Layer w15: v1(-250,250) -250,1050 -150,1150 -150,1650 TP1.1@50,1850
CPOUT: C1LFA.1 C2LFA.1 R16.1 R29.1 U2.2 | length 1614.7
  Top Layer w10: R29.1@-181.27,-391.27 R29.1@-181.27,-388.27
  Top Layer w25: v1(-204,-411) R29.1@-181.27,-388.27
  Bottom Layer w16: U2.2@-492.72,-1225 -400,-1225 ; C2LFA.1@-488.5,-1520 -488.5,-1481.5 -510,-1460 C1LFA.1@-613.5,-1460 R16.1@-613.5,-1400 -450,-1400 -400,-1350 -400,-1225 ; v1(-204,-411) -400,-607 -400,-1225
CSB: R2.2 TP2.1 U1.39 | length 1083
  Top Layer w11: U1.39@68.9,136.81 68.9,174.35 cw(c104.67,174.35) 79.38,199.65
  Top Layer w13: 79.51,199.51 150,270
  Top Layer w15: TP2.1@50,950 150,850 150,270 95,215
  Top Layer w25: TP2.1@50,950 R2.2@50,1068.5
GND: C1.1 C1LF.2 C2.2 C3.2 C3LF.2 C3LFA.1 C4.2 C5.1 C6.2 C7.2 C8.2 C9.1 C11.2 C12.2 C13.1 C14.1 C17.2 C18.2 C19.2 C20.1 C21.2 C22.2 C23.1 C25.2 C26.2 C27.1 C28.1 C29.2 C30.1 C31.2 C36.2 D1.2 J2.6 J3.2 J3.3 J3.4 J3.5 J4.2 J4.3 J4.4 J4.5 J5.2 J5.3 J5.4 J5.5 J6.2 J6.3 J6.4 J6.5 J7.2 J7.3 J7.4 J7.5 J8.2 J9.2 J10.2 J10.3 J10.4 J11.2 J11.3 J11.4 J12.2 J12.3 J12.4 J13.2 J13.3 J13.4 J14.2 J14.3 J14.4 J14.5 J15.2 J15.3 J15.4 J16.2 J16.3 J16.4 J17.2 J17.3 J17.4 J17.5 J18.2 J18.3 J18.4 J18.5 J19.2 J19.3 J19.4 R2LF.1 R12.1 R17.2 R20.1 R31.1 R35.1 R40.2 TP11.1 U1.2 U1.4 U1.6 U1.15 U1.16 U1.27 U1.29 U1.32 U1.35 U1.40 U1.42 U1.47 U1.48 U1.49 U2.4 Y1.2 | length 3361.1
  Top Layer w6: C2.2@-1101.81,1154.19 C2.2@-1101.81,1155.19 ; C4.2@-1000,807.99 -1000,818 ; v1(-334,-90) C25.2@-305.62,-90 ; v1@-225,30 v1(-224,29) C23.1@-209.19,14.69 ; C8.2@-180,607.99 -180,618 ; v1(-102,-287) C19.2@-81.7,-266.7 ; U1.49@-88.58,88.57 v1(-78.74,78.74)
  Top Layer w9: U1.49@-68.9,-68.91 -49.21,-49.22 v1(-39.37,-39.37) ; U1.49@-9.85,9.84 v1(0,0) ; v1(39.37,-39.37) v1(0,0) ; U1.49@88.59,88.58 49.21,49.2 9.84,9.83 v1(0,0)
  Top Layer w10: v1(-202,252) C26.2@-181.7,231.7 ; -148.51,304.51 C17.2@-136.7,292.7 C17.2@-137.7,292.7 ; v1(-132,235) -122,225.5 C18.2@-116.19,219.19 ; v1(-78.74,78.74) -49.22,49.21 U1.49@-9.85,9.84 ; C27.1@-37,301.5 C27.1@-35,303.5 ; C3LF.2@20,302 C3LF.2@20.5,301.5 ; C31.2@70,304.62 C31.2@71,303.62 ; C12.2@182.52,29.53 C12.2@185,32.01
  Top Layer w11: U1.6@-136.81,9.84 U1.49@-9.85,9.84 ; U1.4@-136.81,49.21 U1.49@-49.22,49.21 ; U1.2@-136.81,88.58 U1.49@-88.59,88.58 ; U1.48@-108.27,136.81 U1.47@-88.58,136.81 U1.49@-88.58,88.57 ; U1.49@-68.9,-68.91 U1.15@-68.9,-136.81 -68.9,-160.04 -62.99,-165.94 ; U1.16@-49.21,-136.81 U1.49@-49.21,-49.22 ; U1.49@9.84,9.83 U1.42@9.84,136.81 ; U1.49@39.37,-29.53 U1.29@136.81,-29.53 ; U1.49@39.37,29.53 U1.32@136.81,29.53 C12.2@182.52,29.53 ; U1.49@49.21,49.2 U1.40@49.21,136.81 ; U1.49@78.74,-68.9 U1.27@136.81,-68.9 ; U1.49@88.59,88.58 U1.35@136.81,88.58
  Top Layer w15: C20.1@-62.99,-185 -62.99,-168
  Top Layer w16: v1@-225,30 v1@-224.5,30 ; C14.1@147.99,-185 v1(170,-185)
  Top Layer w18: v1(-63,-206) C20.1@-62.99,-185
  Top Layer w20: -1095,1161 v1(-1087,1169) ; C3.2@-1045.73,1134.77 C3.2@-1044.23,1134.77 ; -1000,818 v1(-1000,830) ; R2LF.1@-436.27,-480.27 R2LF.1@-435.27,-480.27 ; C1LF.2@-309.27,-433.27 C1LF.2@-308.27,-433.27 ; C22.2@-302,52 C22.2@-301.7,51.7 ; v1@-225,30 v1@-217.8,23.06 ; -180,618 v1(-180,630) ; C21.2@-174.3,-230.7 C21.2@-171.7,-230.7 ; v1(-132,235) -124.93,227.93 ; R31.1@-32.73,-432.27 v1(-10,-455) ; C13.1@166.7,-266.7 v1(187,-286) ; C28.1@231.7,213.7 v1(252,234) ; C30.1@246.7,166.7 v1(267,187) ; C11.2@259.7,117.7 v1(280,138)
  Top Layer w23: C31.2@71,303.62 v1(71,335)
  Top Layer w25: C5.1@-1050,831.5 v1(-1050,864) ; C3.2@-1044.23,1134.77 v1(-1022,1157) ; v1(-669,-135) R35.1@-636.5,-135 ; v1(-669,45) R40.2@-636.5,45 ; v1(-459,-503) R2LF.1@-436.27,-480.27 ; R12.1@-422.73,117.73 v1(-400,95) ; v1(-335,52) C22.2@-304,52 ; v1(-334,-90) -322,-90 ; v1(-332,-456) C1LF.2@-309.27,-433.27 ; v1(-270,210) C29.2@-247.27,187.27 ; v1(-250,1200) J2.6@-250,1312.5 ; v1(-202,252) -193.51,243.51 ; v1(-190,-215) C21.2@-174.3,-230.7 ; v1(-157,313) -148.51,304.51 ; C9.1@-130,631.5 v1(-130,664) ; v1(-102,-287) -93.51,-278.51 ; C27.1@-35,303.5 v1(-35,335) ; C3LF.2@20,302 v1(20,335) ; v1(350,1042) D1.2@350,1070.47
  RF GND w20: v1(-456,-1100) -350,-1100 -300,-1150 -300,-1300 -325,-1325 v1(-452,-1325)
  Bottom Layer w16: C3LFA.1@-740,-1521.5 C3LFA.1@-738.5,-1520 ; v1(-600,250) -600,282.68 Y1.2@-550,332.68
  Bottom Layer w20: C36.2@-850,211.5 v1(-850,244) ; v1(-834,-1400) R17.2@-801.5,-1400 ; v1(-834,-1100) C7.2@-801.5,-1100 ; v1(-834,-1040) C6.2@-801.5,-1040 ; v1(-740,-1551) C3LFA.1@-740,-1521.5 ; U2.4@-492.72,-1325 v1(-452,-1325) ; C1.1@-488.5,-1100 v1(-456,-1100) ; R20.1@-488.5,-1040 v1(-456,-1040)
  other v1: -659.05,-1950 -440.95,-1950 -659.05,-1890 -440.95,-1890 -659.05,-1830 -440.95,-1830 -948.36,-1809.45 -300,-1800 300,-1800 700,-1800 900,-1800 -905.91,-1767 -50,-1750 50,-1750 450,-1750 550,-1750 -863.5,-1724.57 64.23,-1657.5 -1102.53,-1655.3 -45,-1650 450,-1650 550,-1650 -1060.07,-1612.85 -300,-1600 300,-1600 700,-1600 900,-1600 1100,-1600 -7.5,-1586.38 135.5,-1586.23 -1017.65,-1570.43 450,-1550 550,-1550 63.4,-1515 206,-1512.5 -1301.55,-1456.28 125,-1450 225,-1450 450,-1450 550,-1450 -1259.07,-1413.82 -100,-1400 700,-1400 900,-1400 1100,-1400 -1216.67,-1371.4 125,-1350 225,-1350 450,-1350 550,-1350 -1456.1,-1301.72 57.29,-1279.29 193.63,-1272.5 1202.5,-1273.33 -1413.65,-1259.28 450,-1250 550,-1250 -1371.22,-1216.85 -12.42,-1208.58 128.34,-1207.11 1273.51,-1203.54 1132.5,-1203.33 300,-1200 700,-1200 1500,-1200 414.51,-1166.04 545.51,-1166.04 -43.99,-1151.04 950,-1150 1050,-1150 57.63,-1136.4 1203.69,-1132.5 882.08,-1120 -1655.25,-1102.55 343.8,-1095.33 483.51,-1093.54 1132.5,-1069.5 -1612.8,-1060.1 -50,-1050 50,-1050 850,-1050 950,-1050 1050,-1050 274.09,-1024.62 412.8,-1022.83 -1570.4,-1017.7 -1100,-1000 700,-1000 1300,-1000 -50,-950 50,-950 250,-950 350,-950 850,-950 950,-950 -1809.6,-948.22 1557,-921.58 -1767.15,-905.78 847.5,-902.5 750,-900 637.5,-875 -1724.72,-863.35 -50,-850 50,-850 250,-850 350,-850 934.12,-850 1485.25,-850 1627.5,-849.08 -1100,-800 -900,-800 -700,-800 600,-800 700,-800 750,-800 850,-800 1415.5,-779.93 1557.5,-779.24 -50,-750 50,-750 250,-750 350,-750 950,-750 1050,-750 1150,-750 1250,-750 1350,-750 875,-710 1485,-707.43 600,-700 700,-700 50,-698 -49,-677.5 1426.48,-661.5 250,-650 350,-650 1050,-650 1150,-650 1250,-650 1350,-650 953,-647 566.88,-637.5 684.5,-625 -19.99,-623.54 122.47,-623.54 850,-615 -1950,-609.05 -1890,-609.05 -1830,-609.05 -1300,-600 -1100,-600 -500,-600 1700,-600 1900,-600 762.08,-582.5 495,-565 635.99,-565 50,-550 150,-550 250,-550 350,-550 921.76,-545 691.08,-512.5 832.5,-511.43 422.5,-493.12 564,-492.71 40.78,-477.77 185.15,-476 324.01,-473.54 762.5,-441.49 618.58,-440 354.38,-425 494,-422.5 112.83,-405.24 254.3,-402.83 -1500,-400 -1300,-400 -700,-400 900,-400 1100,-400 1300,-400 1500,-400 1700,-400 1900,-400 -1950,-390.94 -1890,-390.94 -1830,-390.94 548.5,-370 689,-367.63 282.5,-353.12 424.08,-352.5 183.59,-332.12 478.58,-300 620,-298.93 353.79,-282.5 549,-227.63 406.62,-227.5 -1700,-200 -900,-200 700,-200 300,-197.5 476.37,-156 -1950,-109.06 -1890,-109.06 -1830,-109.06 350,-100 450,-100 550,-100 650,-100 750,-100 850,-100 950,-100 1050,-100 1150,-100 1250,-100 1350,-100 1450,-100 1550,-100 1650,-100 1750,-100 -78.74,-78.74 -39.37,-78.74 0,-78.74 39.37,-78.74 78.74,-78.74 -78.74,-39.37 0,-39.37 78.74,-39.37 -78.74,0 -39.37,0 39.37,0 78.74,0 350,0 450,0 550,0 650,0 750,0 850,0 950,0 1050,0 1150,0 1250,0 1349.71,0 1450,0 1550,0 1650,0 1750,0 -78.74,39.37 -39.37,39.37 0,39.37 39.37,39.37 78.74,39.37 352.5,72.21 -39.37,78.74 0,78.74 39.37,78.74 78.74,78.74 550.5,83.89 420,108.24 -1950,109.06 -1890,109.06 -1830,109.06 480,155.88 622.5,156.6 350,181.03 -1100,200 1100,200 1300,200 1500,200 1700,200 1900,200 498,225 691.5,225.39 551.59,227.5 397,234 767.03,290 621.34,297.5 399.31,299.72 500,299.72 850,300 950,300 1047.5,309 1130.37,353.62 685,357 -1950,390.94 -1890,390.94 -1830,390.94 765,394.5 -1300,400 -500,400 400,399.72 500,399.72 850,400 950,400 1300,400 1500,400 1700,400 1900,400 1202.5,424.28 1060.93,425 506.5,493.5 1130.93,495 1273.22,495 402,500 600,500 682.5,550 1202.5,566.57 1345,566.78 447.5,574 -1500,600 -1300,600 -700,600 525,600 900,600 1700,600 1900,600 598.5,603.14 -1950,609.06 -1890,609.06 -1830,609.06 708.87,637.5 1273.5,637.5 1415,636.78 777.5,707.48 1343.43,707.5 1485.72,707.5 638.5,709.16 848.16,777.5 1555,777.5 707.92,779.07 1415,779.07 -1900,800 -1700,800 -1500,800 -1300,800 -500,800 100,800 500,800 1100,800 1900,800 918,847.69 778.5,849.16 1627.5,849.28 1486,850 849.34,920 990,920 1557,920 1061.37,990 921,991.66 -1700,1000 -1500,1000 -1300,1000 500,1000 700,1000 1300,1000 1131.37,1060 990,1061.66 1060,1131.66 1202.87,1132.5 -1500,1200 -700,1200 100,1200 500,1200 700,1200 900,1200 1500,1200 1272.5,1202.5 1133.5,1204.16 -1370.85,1217.05 -1413.3,1259.5 1201.84,1272.5 -1455.7,1301.9 -1216.59,1371.31 -900,1400 -700,1400 500,1400 700,1400 900,1400 1100,1400 -1259.04,1413.76 -1301.44,1456.16 -1100,1600 -900,1600 -700,1600 -500,1600 -300,1600 100,1600 300,1600 500,1600 700,1600 900,1600 1100,1600 -900,1800 -700,1800 300,1800 500,1800 700,1800 900,1800
LD: R15.2 TP9.1 U1.38 | length 1003.5
  Top Layer w9: U1.38@88.58,131.12 U1.38@88.58,136.81
  Top Layer w11: U1.38@88.58,136.81 88.58,167.01 cw(c103.53,167.01) 92.96,177.58
  Top Layer w13: 92.96,177.58 100.38,185
  Top Layer w15: 100.41,185 185,270 185,885 TP9.1@250,950
  Top Layer w25: TP9.1@250,950 R15.2@250,1068.5
MUTE: R6.2 TP5.1 U1.37 | length 2686.6
  Top Layer w10: 121.35,170.59 cw(c123.18,168.76) 123.18,171.35
  Top Layer w11: U1.37@108.27,136.81 U1.37@108.27,150.5 ; U1.37@108.28,150.5 cw(c127.09,150.5) 113.79,163.8
  Top Layer w13: 113.79,163.8 122.27,172.27
  Top Layer w15: 122.27,172.27 220,270 220,770 350,900 v1(350,950)
  Top Layer w25: R6.2@-350,1731.5 TP5.1@-350,1850
  Bottom Layer w15: TP5.1@-350,1850 -250,1950 200,1950 250,1900 250,1100 350,1000 v1(350,950)
MUXOUT: R4.2 TP3.1 U1.23 | length 3212.8
  Top Layer w11: U1.23@88.58,-136.81 88.58,-177.44 ccw(c127.56,-177.44) v2(100,-205)
  Top Layer w15: v1(200,1200) 350,1200 400,1150 400,900 255,755 v1(255,335)
  Top Layer w16: 90.93,-190.77 ccw(c127.56,-177.44) v2(100,-205)
  Top Layer w25: R4.2@-150,1731.5 TP3.1@-150,1850
  Bottom Layer w15: TP3.1@-150,1850 -80,1920 175,1920 200,1895 v1(200,1200) ; v2(100,-205) 100,-240 115,-255 180,-255 205,-230 205,15 220,30 285,30 310,55 310,220 255,275 v1(255,335)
